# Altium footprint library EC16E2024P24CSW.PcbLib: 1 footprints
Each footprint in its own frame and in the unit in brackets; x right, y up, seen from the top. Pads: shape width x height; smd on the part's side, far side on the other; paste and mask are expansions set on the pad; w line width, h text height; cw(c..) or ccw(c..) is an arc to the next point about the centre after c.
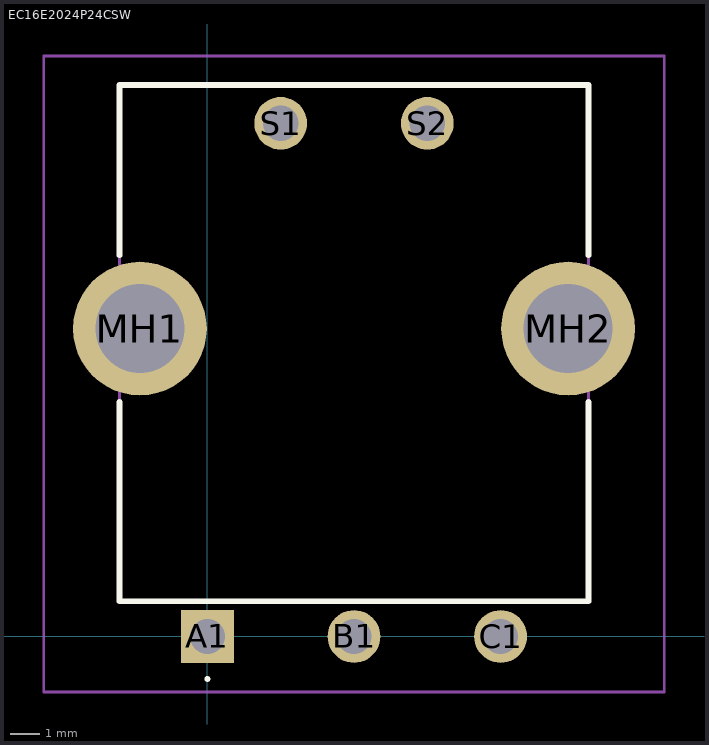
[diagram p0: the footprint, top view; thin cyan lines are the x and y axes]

## EC16E2024P24CSW [mm]
pads (7):
  rect 1.8x1.8 hole 1.2: A1(0,0)
  round 1.8 hole 1.2: B1(5,0) C1(10,0) S1(2.5,17.5) S2(7.5,17.5)
  round 4.56 hole 3.04: MH1(-2.3,10.5) MH2(12.3,10.5)
Top Overlay:
  lines w0.1: 0,-1.5 cw(c0,-1.45) 0,-1.4 ; 0,-1.5 0,-1.5 ; 0,-1.5 ccw(c0,-1.45) 0,-1.4 ; 0,-1.4 0,-1.4
  lines w0.2: -3,8 -3,1.2 13,1.2 13,8 ; -3,13 -3,18.8 13,18.8 13,13
Mechanical 15:
  lines w0.1: -3,1.2 13,1.2 13,18.8 -3,18.8 -3,1.2
Mechanical 20:
  lines w0.1: -5.58,-1.9 15.58,-1.9 15.58,19.8 -5.58,19.8 -5.58,-1.9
